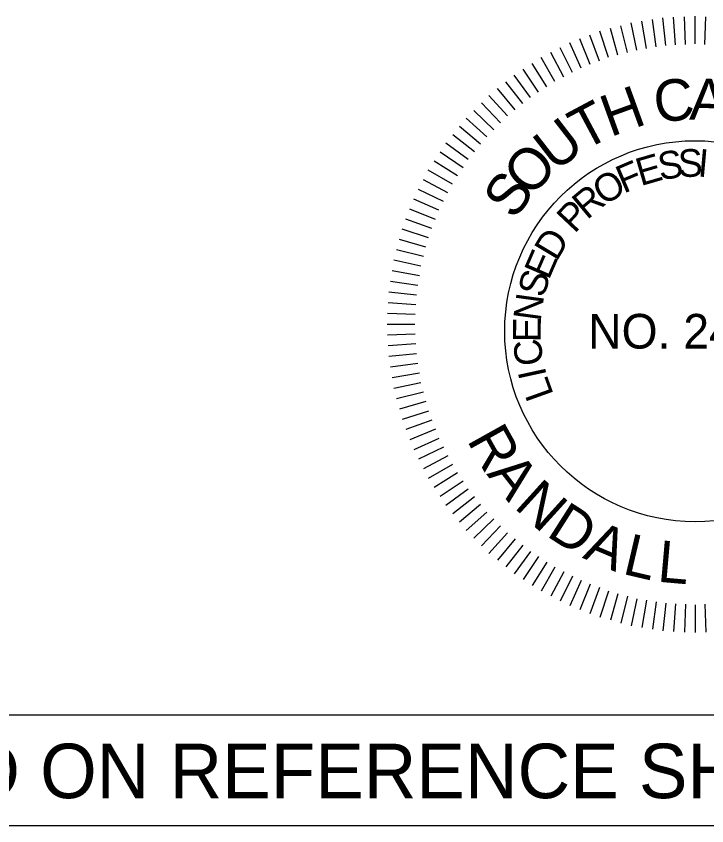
# Model space of a CAD drawing. Extents: x 1964849 to 1967422, y 1116563 to 1122210.
# Drawn here: x 1967242.5 to 1967331.3, y 1119379.6 to 1119483.7 of the extents above; entities that cross this region are included whole.
import ezdxf

# ---------------------------------------------------------------- set-up
doc = ezdxf.new("R2010")
doc.units = 0
doc.layers.add('RD_Sketch1', color=7, linetype='Continuous')
doc.layers.add('RD_TX_PEShield', color=7, linetype='Continuous')

msp = doc.modelspace()

# ---------------------------------------------------------------- linework, layer by layer
at = {"layer": 'RD_Sketch1'}
msp.add_lwpolyline([(1967062.99, 1119393.87), (1967363.41, 1119393.87), (1967363.41, 1119379.61), (1967062.99, 1119379.61)], close=True, dxfattribs=at)
at = {"layer": 'RD_TX_PEShield'}
for p, q in [((1967325.98, 1119479.89), (1967325.61, 1119483.43)), ((1967325.98, 1119479.89), (1967325.61, 1119483.43)), ((1967327.24, 1119479.96), (1967326.99, 1119483.51)), ((1967327.24, 1119479.96), (1967326.99, 1119483.51)), ((1967328.5, 1119480.02), (1967328.37, 1119483.58)), ((1967328.5, 1119480.02), (1967328.37, 1119483.58)), ((1967329.75, 1119480.09), (1967329.75, 1119483.65)), ((1967329.75, 1119480.09), (1967329.75, 1119483.65)), ((1967331.01, 1119480.02), (1967331.13, 1119483.58)), ((1967331.01, 1119480.02), (1967331.13, 1119483.58)), ((1967321.04, 1119478.98), (1967320.18, 1119482.43)), ((1967321.04, 1119478.98), (1967320.18, 1119482.43)), ((1967322.26, 1119479.3), (1967321.52, 1119482.79)), ((1967322.26, 1119479.3), (1967321.52, 1119482.79)), ((1967323.5, 1119479.5), (1967322.88, 1119483)), ((1967323.5, 1119479.5), (1967322.88, 1119483)), ((1967324.74, 1119479.7), (1967324.25, 1119483.22)), ((1967324.74, 1119479.7), (1967324.25, 1119483.22)), ((1967318.61, 1119478.33), (1967317.51, 1119481.71)), ((1967318.61, 1119478.33), (1967317.51, 1119481.71)), ((1967319.83, 1119478.65), (1967318.85, 1119482.07)), ((1967319.83, 1119478.65), (1967318.85, 1119482.07)), ((1967315.09, 1119476.97), (1967313.64, 1119480.23)), ((1967315.09, 1119476.97), (1967313.64, 1119480.23)), ((1967316.27, 1119477.43), (1967314.93, 1119480.72)), ((1967316.27, 1119477.43), (1967314.93, 1119480.72)), ((1967317.44, 1119477.88), (1967316.22, 1119481.22)), ((1967317.44, 1119477.88), (1967316.22, 1119481.22)), ((1967313.97, 1119476.4), (1967312.41, 1119479.6)), ((1967313.97, 1119476.4), (1967312.41, 1119479.6)), ((1967311.73, 1119475.26), (1967309.95, 1119478.34)), ((1967311.73, 1119475.26), (1967309.95, 1119478.34)), ((1967312.85, 1119475.83), (1967311.18, 1119478.97)), ((1967312.85, 1119475.83), (1967311.18, 1119478.97)), ((1967310.67, 1119474.58), (1967308.79, 1119477.59)), ((1967310.67, 1119474.58), (1967308.79, 1119477.59)), ((1967308.57, 1119473.21), (1967306.47, 1119476.09)), ((1967308.57, 1119473.21), (1967306.47, 1119476.09)), ((1967309.62, 1119473.89), (1967307.63, 1119476.84)), ((1967309.62, 1119473.89), (1967307.63, 1119476.84)), ((1967307.59, 1119472.41), (1967305.4, 1119475.22)), ((1967307.59, 1119472.41), (1967305.4, 1119475.22)), ((1967306.61, 1119471.62), (1967304.33, 1119474.35)), ((1967306.61, 1119471.62), (1967304.33, 1119474.35)), ((1967305.63, 1119470.83), (1967303.25, 1119473.48)), ((1967305.63, 1119470.83), (1967303.25, 1119473.48)), ((1967304.74, 1119469.94), (1967302.27, 1119472.5)), ((1967304.74, 1119469.94), (1967302.27, 1119472.5)), ((1967303.86, 1119469.05), (1967301.3, 1119471.52)), ((1967303.86, 1119469.05), (1967301.3, 1119471.52)), ((1967302.97, 1119468.16), (1967300.32, 1119470.55)), ((1967302.97, 1119468.16), (1967300.32, 1119470.55)), ((1967302.17, 1119467.19), (1967299.45, 1119469.47)), ((1967302.17, 1119467.19), (1967299.45, 1119469.47)), ((1967301.38, 1119466.21), (1967298.58, 1119468.4)), ((1967301.38, 1119466.21), (1967298.58, 1119468.4)), ((1967300.59, 1119465.23), (1967297.71, 1119467.32)), ((1967300.59, 1119465.23), (1967297.71, 1119467.32)), ((1967299.91, 1119464.18), (1967296.96, 1119466.17)), ((1967299.91, 1119464.18), (1967296.96, 1119466.17)), ((1967299.22, 1119463.12), (1967296.21, 1119465.01)), ((1967299.22, 1119463.12), (1967296.21, 1119465.01)), ((1967298.54, 1119462.07), (1967295.45, 1119463.85)), ((1967298.54, 1119462.07), (1967295.45, 1119463.85)), ((1967297.97, 1119460.95), (1967294.83, 1119462.62)), ((1967297.97, 1119460.95), (1967294.83, 1119462.62)), ((1967297.4, 1119459.83), (1967294.2, 1119461.39)), ((1967297.4, 1119459.83), (1967294.2, 1119461.39)), ((1967296.82, 1119458.71), (1967293.57, 1119460.15)), ((1967296.82, 1119458.71), (1967293.57, 1119460.15)), ((1967296.37, 1119457.53), (1967293.08, 1119458.86)), ((1967296.37, 1119457.53), (1967293.08, 1119458.86)), ((1967295.92, 1119456.36), (1967292.58, 1119457.57)), ((1967295.92, 1119456.36), (1967292.58, 1119457.57)), ((1967295.47, 1119455.18), (1967292.09, 1119456.28)), ((1967295.47, 1119455.18), (1967292.09, 1119456.28)), ((1967295.15, 1119453.97), (1967291.73, 1119454.95)), ((1967295.15, 1119453.97), (1967291.73, 1119454.95)), ((1967294.82, 1119452.76), (1967291.37, 1119453.62)), ((1967294.82, 1119452.76), (1967291.37, 1119453.62)), ((1967294.5, 1119451.54), (1967291.01, 1119452.28)), ((1967294.5, 1119451.54), (1967291.01, 1119452.28)), ((1967294.3, 1119450.3), (1967290.8, 1119450.91)), ((1967294.3, 1119450.3), (1967290.8, 1119450.91)), ((1967294.1, 1119449.06), (1967290.58, 1119449.55)), ((1967294.1, 1119449.06), (1967290.58, 1119449.55)), ((1967293.91, 1119447.81), (1967290.36, 1119448.19)), ((1967293.91, 1119447.81), (1967290.36, 1119448.19)), ((1967293.84, 1119446.56), (1967290.29, 1119446.8)), ((1967293.84, 1119446.56), (1967290.29, 1119446.8)), ((1967293.77, 1119445.3), (1967290.22, 1119445.43)), ((1967293.77, 1119445.3), (1967290.22, 1119445.43)), ((1967293.71, 1119444.05), (1967290.15, 1119444.05)), ((1967293.71, 1119444.05), (1967290.15, 1119444.05)), ((1967293.77, 1119442.79), (1967290.22, 1119442.67)), ((1967293.77, 1119442.79), (1967290.22, 1119442.67)), ((1967293.84, 1119441.53), (1967290.29, 1119441.29)), ((1967293.84, 1119441.53), (1967290.29, 1119441.29)), ((1967293.91, 1119440.28), (1967290.36, 1119439.91)), ((1967293.91, 1119440.28), (1967290.36, 1119439.91)), ((1967294.1, 1119439.04), (1967290.58, 1119438.54)), ((1967294.1, 1119439.04), (1967290.58, 1119438.54)), ((1967294.3, 1119437.79), (1967290.8, 1119437.18)), ((1967294.3, 1119437.79), (1967290.8, 1119437.18)), ((1967294.5, 1119436.55), (1967291.01, 1119435.81)), ((1967294.5, 1119436.55), (1967291.01, 1119435.81)), ((1967294.82, 1119435.34), (1967291.37, 1119434.48)), ((1967294.82, 1119435.34), (1967291.37, 1119434.48)), ((1967295.15, 1119434.12), (1967291.73, 1119433.14)), ((1967295.15, 1119434.12), (1967291.73, 1119433.14)), ((1967295.47, 1119432.91), (1967292.09, 1119431.81)), ((1967295.92, 1119431.73), (1967292.58, 1119430.52)), ((1967295.92, 1119431.73), (1967292.58, 1119430.52)), ((1967296.37, 1119430.56), (1967293.08, 1119429.23)), ((1967296.37, 1119430.56), (1967293.08, 1119429.23)), ((1967296.82, 1119429.38), (1967293.57, 1119427.94)), ((1967296.82, 1119429.38), (1967293.57, 1119427.94)), ((1967297.4, 1119428.26), (1967294.2, 1119426.71)), ((1967297.4, 1119428.26), (1967294.2, 1119426.71)), ((1967297.97, 1119427.14), (1967294.83, 1119425.47)), ((1967297.97, 1119427.14), (1967294.83, 1119425.47)), ((1967298.54, 1119426.02), (1967295.45, 1119424.24)), ((1967298.54, 1119426.02), (1967295.45, 1119424.24)), ((1967299.22, 1119424.97), (1967296.21, 1119423.08)), ((1967299.22, 1119424.97), (1967296.21, 1119423.08)), ((1967299.91, 1119423.91), (1967296.96, 1119421.93)), ((1967299.91, 1119423.91), (1967296.96, 1119421.93)), ((1967300.59, 1119422.86), (1967297.71, 1119420.77)), ((1967300.59, 1119422.86), (1967297.71, 1119420.77)), ((1967301.38, 1119421.88), (1967298.58, 1119419.69)), ((1967301.38, 1119421.88), (1967298.58, 1119419.69)), ((1967302.17, 1119420.9), (1967299.45, 1119418.62)), ((1967302.17, 1119420.9), (1967299.45, 1119418.62)), ((1967302.97, 1119419.93), (1967300.32, 1119417.54)), ((1967302.97, 1119419.93), (1967300.32, 1119417.54)), ((1967303.86, 1119419.04), (1967301.3, 1119416.57)), ((1967303.86, 1119419.04), (1967301.3, 1119416.57)), ((1967304.74, 1119418.15), (1967302.27, 1119415.59)), ((1967304.74, 1119418.15), (1967302.27, 1119415.59)), ((1967305.63, 1119417.26), (1967303.25, 1119414.61)), ((1967305.63, 1119417.26), (1967303.25, 1119414.61)), ((1967306.61, 1119416.47), (1967304.33, 1119413.74)), ((1967306.61, 1119416.47), (1967304.33, 1119413.74)), ((1967307.59, 1119415.68), (1967305.4, 1119412.87)), ((1967307.59, 1119415.68), (1967305.4, 1119412.87)), ((1967308.57, 1119414.88), (1967306.47, 1119412)), ((1967308.57, 1119414.88), (1967306.47, 1119412)), ((1967309.62, 1119414.2), (1967307.63, 1119411.25)), ((1967309.62, 1119414.2), (1967307.63, 1119411.25)), ((1967310.67, 1119413.51), (1967308.79, 1119410.5)), ((1967310.67, 1119413.51), (1967308.79, 1119410.5)), ((1967311.73, 1119412.83), (1967309.95, 1119409.75)), ((1967311.73, 1119412.83), (1967309.95, 1119409.75)), ((1967312.85, 1119412.26), (1967311.18, 1119409.12)), ((1967312.85, 1119412.26), (1967311.18, 1119409.12)), ((1967313.97, 1119411.69), (1967312.41, 1119408.49)), ((1967313.97, 1119411.69), (1967312.41, 1119408.49)), ((1967315.09, 1119411.12), (1967313.64, 1119407.86)), ((1967315.09, 1119411.12), (1967313.64, 1119407.86)), ((1967316.27, 1119410.67), (1967314.93, 1119407.37)), ((1967316.27, 1119410.67), (1967314.93, 1119407.37)), ((1967317.44, 1119410.22), (1967316.22, 1119406.87)), ((1967317.44, 1119410.22), (1967316.22, 1119406.87)), ((1967318.61, 1119409.76), (1967317.51, 1119406.38)), ((1967318.61, 1119409.76), (1967317.51, 1119406.38)), ((1967319.83, 1119409.44), (1967318.85, 1119406.02)), ((1967319.83, 1119409.44), (1967318.85, 1119406.02)), ((1967321.04, 1119409.11), (1967320.18, 1119405.66)), ((1967321.04, 1119409.11), (1967320.18, 1119405.66)), ((1967322.26, 1119408.79), (1967321.52, 1119405.31)), ((1967322.26, 1119408.79), (1967321.52, 1119405.31)), ((1967323.5, 1119408.59), (1967322.88, 1119405.09)), ((1967323.5, 1119408.59), (1967322.88, 1119405.09)), ((1967324.74, 1119408.39), (1967324.25, 1119404.87)), ((1967324.74, 1119408.39), (1967324.25, 1119404.87)), ((1967325.98, 1119408.2), (1967325.61, 1119404.66)), ((1967325.98, 1119408.2), (1967325.61, 1119404.66)), ((1967327.24, 1119408.13), (1967326.99, 1119404.59)), ((1967327.24, 1119408.13), (1967326.99, 1119404.59)), ((1967328.5, 1119408.07), (1967328.37, 1119404.51)), ((1967328.5, 1119408.07), (1967328.37, 1119404.51)), ((1967329.75, 1119408), (1967329.75, 1119404.44)), ((1967329.75, 1119408), (1967329.75, 1119404.44)), ((1967331.01, 1119408.07), (1967331.13, 1119404.51)), ((1967331.01, 1119408.07), (1967331.13, 1119404.51))]:
    msp.add_line(p, q, dxfattribs=at)
msp.add_circle((1967329.75, 1119443.17), 24.48, dxfattribs=at)

# ---------------------------------------------------------------- texts
at = {"layer": 'RD_Sketch1'}
msp.add_text('ALIGNMENT CONTROL CAN BE FOUND ON REFERENCE SHEET', height=7, dxfattribs=at).set_placement((1967066.64, 1119383.16))
at = {"layer": 'RD_TX_PEShield'}
for s, height, rotation, p in [('C', 5.34, 6.8832, (1967324.75, 1119469.91)), ('A', 5.34, 357.9448, (1967328.96, 1119470.36)), ('H', 5.34, 19.9102, (1967318.85, 1119468.09)), ('T', 5.34, 28.0947, (1967315.41, 1119466.28)), ('U', 5.34, 37.7726, (1967311.73, 1119463.54)), ('O', 5.34, 47.4504, (1967308.56, 1119460.22)), ('E', 3.56, 16.1843, (1967322.75, 1119461.8)), ('S', 3.56, 8.6909, (1967325.24, 1119462.56)), ('S', 3.56, 1.79, (1967327.6, 1119462.96)), ('I', 3.56, 354.889, (1967330, 1119463.07)), ('F', 3.56, 23.0853, (1967320.56, 1119460.83)), ('O', 3.56, 31.7869, (1967318, 1119459.23)), ('S', 5.34, 54.9027, (1967306.53, 1119457.33)), ('R', 3.56, 39.8902, (1967315.85, 1119457.41)), ('P', 3.56, 46.7912, (1967314.24, 1119455.64)), ('D', 3.56, 59.074, (1967311.94, 1119452.05)), ('E', 3.56, 66.5674, (1967310.93, 1119449.66)), ('S', 3.56, 73.4683, (1967310.29, 1119447.35)), ('N', 3.56, 82.17, (1967309.88, 1119444.35)), ('E', 3.56, 89.6633, (1967309.9, 1119441.75)), ('C', 3.56, 97.7667, (1967310.29, 1119438.97)), ('I', 3.56, 102.2511, (1967310.68, 1119437.46)), ('L', 3.56, 109.7445, (1967311.59, 1119435.02)), ('R', 5.34, 299.1493, (1967300.35, 1119429.19)), ('A', 5.34, 308.0877, (1967302.88, 1119424.8)), ('N', 5.34, 317.7655, (1967306.35, 1119420.54)), ('D', 5.34, 327.4433, (1967310.49, 1119416.93)), ('A', 5.34, 337.1212, (1967315.17, 1119414.06)), ('L', 5.34, 346.799, (1967320.27, 1119412.02)), ('L', 5.34, 354.9835, (1967324.8, 1119410.99))]:
    msp.add_text(s, height=height, rotation=rotation, dxfattribs=at).set_placement(p)
msp.add_text('NO. 24265', height=4.45, dxfattribs=at).set_placement((1967316, 1119440.94))

doc.saveas('drawing.dxf')
